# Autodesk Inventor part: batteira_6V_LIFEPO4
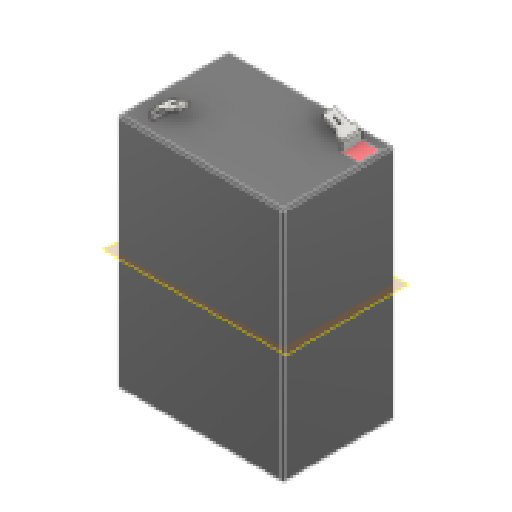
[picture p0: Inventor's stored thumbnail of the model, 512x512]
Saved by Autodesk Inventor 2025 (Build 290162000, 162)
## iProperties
Created: 2025-05
Part Number: batteira_6V_LIFEPO4
Material: Plastica ABS
Document SubType Name: Modeling
Designer: R5800u
Density: 1.06 g/cm^3
Appearance: Liscia - Nero
Author: R5800u
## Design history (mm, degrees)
sketch "Schizzo1"
  geometry: L1 (35, 23.5)-(-35, 23.5); L2 (-35, 23.5)-(-35, -23.5); L3 (-35, -23.5)-(35, -23.5); L4 (35, -23.5)-(35, 23.5); L5 (35, 23.5)-(-35, -23.5); L6 (-35, 23.5)-(35, -23.5); 1 further point
  constraints: 12 end point, 2 midpoint, 2 parallel, 1 horizontal, 1 perpendicular
  dimensions: "d0" = 70 distance of L3.end L2.end; "d1" = 47 distance of L2.end L1.end
extrude "Estrusione1" new body sketch "Schizzo1" distance "d2" = 100; taper "d3" = 0 deg
fillet "Raccordo1" dims "d4" = 1
node "Piano di lavoro1"
sketch "Schizzo2"
  geometry: L1 (0, 99)-(68, 99) reference; L2 (9, 99)-(19, 99); L3 (-1, 0)-(-1, 98) reference; L4 (9, 99)-(9, 102); L5 (9, 102)-(18.063, 106.226); L6 (9, 102)-(19, 102); L7 (17.64, 107.132)-(8, 102.637); L8 (8, 102.637)-(8, 98); L9 (8, 98)-(19, 98); L10 (17.64, 107.132)-(18.063, 106.226); 3 further points
  constraints: 16 end point, 2 horizontal, 2 perpendicular, 1 equal length, 1 point on line, 2 other
  dimensions: "d8" = 10 distance from line of L3 L2.start; "d9" = 3 distance of L2.start L4.end; "d10" = 10 distance of L4.end L5.end; "d11" = 25 deg angle of L6 L5; "d12" = 1 distance between parallel lines of L5 L7
extrude "Estrusione2" new body sketch "Schizzo2" distance "d13" = 8; taper "d14" = 0 deg
sketch "Schizzo3"
  geometry: L1 (0, 8)-(10.637, 8) reference; L2 (0, 8)-(0, 0) reference; L3 (10.637, 0)-(0, 0) reference; L4 (10.637, 8)-(10.637, 0) reference; L5 (7.143, 1.097)-(0, 1.097); L6 (0.058, 12)-(0.058, -33) reference; L7 (0.058, 6.71)-(7.201, 6.71); L8 (7.201, 6.71)-(7.201, 8); L9 (7.143, 1.097)-(7.143, 0); L10 (5.749, 3.143)-(2.506, 3.143); L11 (2.506, 3.143)-(2.506, 4.234); L12 (2.506, 4.234)-(5.749, 4.234); L13 (5.749, 4.234)-(5.749, 3.143); L14 (5.749, 3.143)-(2.506, 4.234); L15 (2.506, 3.143)-(5.749, 4.234); L16 (0, 0)-(-2.978, 0); L17 (-2.978, 0)-(-2.978, 8); L18 (-2.978, 8)-(0, 8); L19 (0, 8)-(0, 0); L20 (0.058, 6.71)-(0, 6.71); 7 further points
  constraints: 30 end point, 7 perpendicular, 5 point on line, 4 parallel, 2 horizontal, 2 midpoint
extrude "Estrusione3" cut sketch "Schizzo3" distance "d15" = 2; taper "d16" = 0 deg
fillet "Raccordo2" dims "d17" = 1
mirror "Speculare3"
mirror "Speculare4"
sketch "Schizzo4"
  geometry: L1 (28.239, -20.341)-(12.198, -20.341); L2 (12.198, -20.341)-(12.198, -6.458); L3 (12.198, -6.458)-(28.239, -6.458); L4 (28.239, -6.458)-(28.239, -20.341); L5 (-7.969, 6.675)-(-29.451, 6.675); L6 (-29.451, 6.675)-(-29.451, 21.121); L7 (-29.451, 21.121)-(-7.969, 21.121); L8 (-7.969, 21.121)-(-7.969, 6.675); 1 further point
  constraints: 16 end point, 4 parallel, 2 horizontal, 2 perpendicular
extrude "Estrusione4" cut sketch "Schizzo4" distance "d18" = 10; taper "d19" = 0 deg
fillet "Raccordo3" dims "d20" = 1
sketch "Schizzo5"
  geometry: L1 (26.031, 10.057)-(33.227, 10.057); L2 (33.227, 10.057)-(33.227, 18.869); L3 (33.227, 18.869)-(26.031, 18.869); L4 (26.031, 18.869)-(26.031, 10.057); 1 further point
  constraints: 8 end point, 2 parallel, 1 horizontal, 1 perpendicular
extrude "Estrusione5" cut sketch "Schizzo5" distance "d21" = 0.1; taper "d22" = 0 deg
sketch "Schizzo6"
  geometry: L1 (-34.297, 72.049)-(102.974, 72.049); L2 (102.974, 72.049)-(102.974, 31.804); L3 (102.974, 31.804)-(-34.297, 31.804); L4 (-34.297, 31.804)-(-34.297, 72.049); 1 further point
  constraints: 2 other
extrude "Estrusione6" cut sketch "Schizzo6" distance "d23" = 0.1; taper "d24" = 0 deg
node "Piano di lavoro2"
node "Solido1"
node "Solido2"
node "Linea chiusa proiettata1"
other parameters: "d5" = -5
